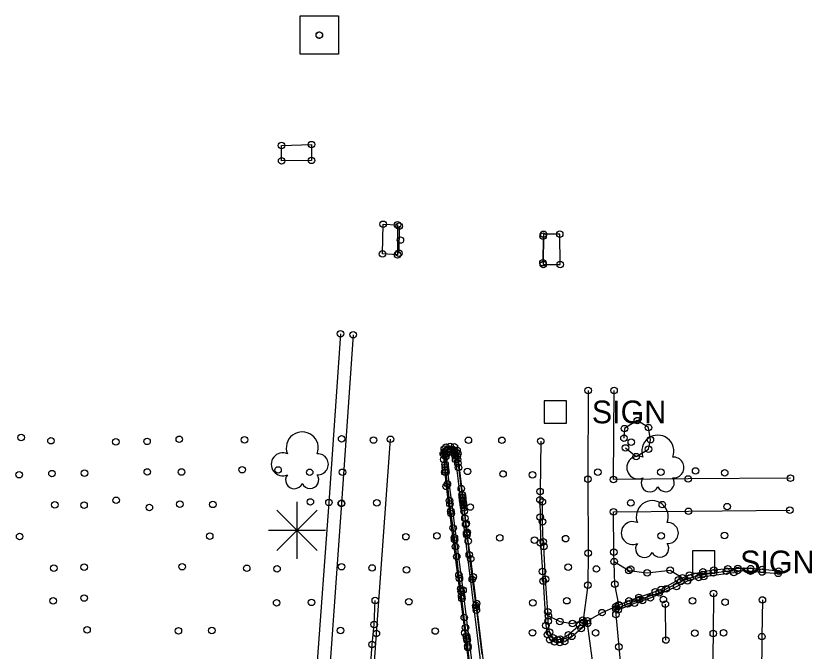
# Model space of a CAD drawing. Extents: x 20503438 to 20508873, y 7964251 to 7984667.
# Drawn here: x 20507965.8 to 20508210.3, y 7970777.7 to 7970972.7 of the extents above; entities that cross this region are included whole.
import ezdxf

# ---------------------------------------------------------------- set-up
doc = ezdxf.new("R2010")
doc.units = 0
for name, color, linetype in [('Default', 7, 'Continuous'), ('SurConcreteSlab', 7, 'Continuous'), ('SurControl', 7, 'Continuous'), ('SurEdgeCurb', 7, 'Continuous'), ('SurEdgeRoadPaved', 7, 'Continuous'), ('SurEdgeSidewalk', 7, 'Continuous'), ('SurMiscStructureLine', 7, 'Continuous'), ('SurNaturalCells', 7, 'Continuous'), ('SurPointsNonDTM', 7, 'Continuous'), ('SurRoadPoints', 7, 'Continuous'), ('SurSurveyPoints', 7, 'Continuous')]:
    doc.layers.add(name, color=color, linetype=linetype)

msp = doc.modelspace()

# ---------------------------------------------------------------- linework, layer by layer
at = {"layer": 'Default'}
msp.add_line((20508058.96, 7970966.8), (20508058.96, 7970966.8), dxfattribs=at)
at = {"layer": 'SurConcreteSlab'}
for points in [[(20508056.53, 7970933.17), (20508056.56, 7970928.33), (20508047.39, 7970928.17), (20508047.33, 7970932.91)], [(20508083.01, 7970899.32), (20508078.36, 7970899.58), (20508078.56, 7970908.71), (20508082.97, 7970908.56)], [(20508127.76, 7970896.34), (20508132.91, 7970896.34), (20508132.8, 7970905.69), (20508127.8, 7970905.63)]]:
    msp.add_lwpolyline(points, close=True, dxfattribs=at)
for points in [[(20508107.6, 7970759.96), (20508103.11, 7970796.34), (20508097.78, 7970837.4), (20508098.06, 7970838.21), (20508098.58, 7970838.71), (20508099.2, 7970838.8), (20508099.97, 7970838.59), (20508100.61, 7970837.86), (20508100.82, 7970836.46), (20508109.87, 7970762.52)], [(20508180.03, 7970795.32), (20508179.96, 7970783.05), (20508179.7, 7970770.56)], [(20508195.04, 7970793.34), (20508194.87, 7970782.09), (20508194.73, 7970769.54), (20508194.52, 7970745.32), (20508194.45, 7970720.76), (20508194.31, 7970696.25), (20508194.23, 7970684.32), (20508194.1, 7970672.27)], [(20508165.42, 7970781.05), (20508165.24, 7970792.03)], [(20508149.99, 7970790.58), (20508150.07, 7970788.88), (20508150.96, 7970778.93), (20508151.97, 7970767.58), (20508152.03, 7970767.48)], [(20508145.82, 7970759.71), (20508145.05, 7970760.17), (20508144.51, 7970760.43), (20508142.73, 7970775.46), (20508141.37, 7970786.17), (20508141.29, 7970786.96)]]:
    msp.add_lwpolyline(points, dxfattribs=at)
at = {"layer": 'SurControl'}
for p, q in [((20508053.08, 7970960.92), (20508053.08, 7970972.68)), ((20508053.08, 7970972.68), (20508064.84, 7970972.68)), ((20508064.84, 7970972.68), (20508064.84, 7970960.92)), ((20508064.84, 7970960.92), (20508053.08, 7970960.92))]:
    msp.add_line(p, q, dxfattribs=at)
at = {"layer": 'SurEdgeCurb'}
for points in [[(20508083.52, 7970908.1), (20508083.37, 7970899.81)], [(20508127.68, 7970905.03), (20508127.64, 7970896.9)], [(20508111.46, 7970757.58), (20508107.28, 7970792.25), (20508106.19, 7970800.48), (20508105.45, 7970805.96), (20508104.72, 7970811.44), (20508104.41, 7970814.12), (20508104.09, 7970816.8), (20508101.55, 7970838.26), (20508101.25, 7970839.35), (20508100.43, 7970840.39), (20508099.17, 7970840.52), (20508097.87, 7970840.26), (20508097.34, 7970839.65), (20508097.04, 7970838.22), (20508097.19, 7970836.5), (20508097.53, 7970832.6), (20508097.91, 7970828.23), (20508103.64, 7970783.23), (20508112.06, 7970713.3)], [(20508105.3, 7970772.87), (20508104.62, 7970778.66), (20508104.56, 7970779.17), (20508104.35, 7970781.01), (20508104.28, 7970781.52), (20508104.19, 7970782.26), (20508103.87, 7970784.83), (20508103.49, 7970787.93), (20508102.76, 7970793.8), (20508102.67, 7970794.53), (20508102.48, 7970795.99), (20508102.38, 7970796.8), (20508101.98, 7970799.94), (20508101.84, 7970801.03), (20508101.15, 7970806.66), (20508100.77, 7970809.73), (20508100.52, 7970811.77), (20508100.44, 7970812.43), (20508100.05, 7970815.43), (20508099.46, 7970819.9), (20508099.36, 7970820.63), (20508099.08, 7970822.82), (20508098.94, 7970823.85), (20508098.29, 7970828.97), (20508097.84, 7970832.56), (20508097.75, 7970833.29), (20508097.64, 7970834.17), (20508097.58, 7970834.97), (20508097.36, 7970837.9), (20508097.55, 7970838.82), (20508098.33, 7970839.5), (20508099.36, 7970839.58), (20508100.31, 7970839.32), (20508100.89, 7970838.7), (20508101.3, 7970837.55), (20508101.41, 7970836.54), (20508101.53, 7970835.38), (20508101.69, 7970833.99), (20508102.56, 7970827.54), (20508102.81, 7970825.63), (20508102.91, 7970824.9), (20508102.94, 7970824.68), (20508103.01, 7970824.09), (20508103.06, 7970823.73), (20508103.12, 7970823.14), (20508103.17, 7970822.77), (20508103.19, 7970822.55), (20508103.3, 7970821.67), (20508103.43, 7970820.57), (20508103.68, 7970818.44), (20508103.9, 7970816.53), (20508104.21, 7970813.88), (20508104.28, 7970813.36), (20508105.02, 7970807.18), (20508105.94, 7970799.68), (20508107.02, 7970791.61), (20508107.09, 7970791.02), (20508107.19, 7970790.21), (20508108.89, 7970776.65)], [(20508138.93, 7970785.58), (20508135.45, 7970782.64), (20508132.99, 7970781.31), (20508132.08, 7970781.12), (20508130.81, 7970781.73), (20508129.68, 7970783.47), (20508129.26, 7970786.83), (20508129.14, 7970789.75), (20508128.46, 7970799.76), (20508127.89, 7970809.74), (20508127.75, 7970811.24), (20508127.5, 7970817.38), (20508127.46, 7970823.44)], [(20508149.99, 7970790.58), (20508153.75, 7970792.12), (20508157.28, 7970793.47), (20508163.38, 7970795.55), (20508165.47, 7970796.77), (20508170.01, 7970799.06), (20508172.82, 7970800.16), (20508176.73, 7970801.21), (20508179.99, 7970801.7), (20508183.98, 7970802.14), (20508187.46, 7970802.38), (20508191.43, 7970802.21), (20508194.93, 7970801.92), (20508199.87, 7970801.51)], [(20508200.05, 7970802.19), (20508194.93, 7970802.74), (20508191.44, 7970802.96), (20508187.48, 7970803.05), (20508184.47, 7970802.89), (20508180.15, 7970802.48), (20508176.8, 7970801.99), (20508172.65, 7970800.98), (20508169.3, 7970799.57), (20508163.96, 7970796.59), (20508162.15, 7970795.85), (20508157.13, 7970794.15), (20508154.07, 7970793.08), (20508151.1, 7970791.7), (20508150.05, 7970791.29)], [(20508074.19, 7970764.53), (20508074.45, 7970769.71), (20508075.14, 7970779.7), (20508075.83, 7970785.82), (20508076.14, 7970793.2)]]:
    msp.add_lwpolyline(points, dxfattribs=at)
at = {"layer": 'SurEdgeRoadPaved'}
for points in [[(20508004.64, 7970575.98), (20508007.59, 7970576.24), (20508010.15, 7970576.78), (20508012.71, 7970577.32), (20508023.73, 7970580.41), (20508026.58, 7970581.33), (20508029.43, 7970582.25), (20508043.66, 7970586.87), (20508052.12, 7970591.56), (20508057.59, 7970595.51), (20508062.67, 7970600.63), (20508065.66, 7970604.97), (20508069.09, 7970611.13), (20508071.43, 7970616.3), (20508072.6, 7970620.21), (20508073.47, 7970624.24), (20508074.25, 7970633.1), (20508074.72, 7970680.34), (20508074.97, 7970737.67), (20508075.09, 7970747.61), (20508075.12, 7970749.94), (20508075.43, 7970766.91), (20508076.47, 7970783.01), (20508080.81, 7970842.69)], [(20508126.95, 7970842.14), (20508126.76, 7970826.65), (20508126.73, 7970824.07), (20508126.8, 7970818.79), (20508126.9, 7970810.87), (20508127.5, 7970802.09), (20508127.7, 7970799.17), (20508128.55, 7970785.48), (20508129.03, 7970782.71), (20508129.77, 7970781.14), (20508131.16, 7970780.45), (20508132.8, 7970780.27), (20508134.32, 7970780.62), (20508136.49, 7970782.18), (20508139.4, 7970784.57), (20508141.37, 7970786.17)], [(20508150.73, 7970790.34), (20508155.76, 7970792.38), (20508158.2, 7970793.19), (20508160.63, 7970793.99), (20508168.7, 7970797.46), (20508172.04, 7970799.24), (20508175.47, 7970800.24), (20508177.05, 7970800.52), (20508186.24, 7970801.76)]]:
    msp.add_lwpolyline(points, dxfattribs=at)
at = {"layer": 'SurEdgeSidewalk'}
for points in [[(20508065.45, 7970875.11), (20508061.91, 7970823.31), (20508058.11, 7970771.65), (20508057.66, 7970725.29), (20508057.57, 7970688.87), (20508054.09, 7970657.04), (20508050.99, 7970628.26), (20508043.75, 7970610.25), (20508036.32, 7970592.17), (20508028.13, 7970591.62), (20508019.27, 7970591.01), (20508019.15, 7970583.11), (20508026.86, 7970581.98)], [(20508069.38, 7970874.8), (20508065.82, 7970823.03), (20508062.04, 7970771.3), (20508061.58, 7970725.29), (20508061.4, 7970688.47), (20508058, 7970656.9), (20508054.87, 7970627.29), (20508047.37, 7970608.68), (20508040.75, 7970592.45), (20508053.1, 7970593.13)], [(20508141.52, 7970857.69), (20508141.46, 7970830.46), (20508141.56, 7970807.74), (20508141.44, 7970797.89), (20508139.87, 7970786.4), (20508141.29, 7970786.96), (20508145.79, 7970789.47), (20508150.05, 7970791.29), (20508150.97, 7970791.83), (20508149.75, 7970798.22), (20508149.41, 7970808.04), (20508149.33, 7970820.39), (20508172.37, 7970820.58), (20508203.46, 7970820.93)], [(20508203.64, 7970830.72), (20508172.24, 7970830.5), (20508149.32, 7970830.31), (20508149.48, 7970857.64)]]:
    msp.add_lwpolyline(points, dxfattribs=at)
at = {"layer": 'SurMiscStructureLine'}
for points in [[(20508153, 7970840.03), (20508156.3, 7970837.36), (20508160.09, 7970839.65), (20508160.65, 7970842.55), (20508160.08, 7970846.27), (20508156.62, 7970848.41), (20508152.7, 7970845.96), (20508152.53, 7970843.04)], [(20508149.53, 7970805.12), (20508154, 7970802.36), (20508159.66, 7970801.67), (20508166.73, 7970802.52), (20508170.52, 7970800.18)], [(20508129.31, 7970788.44), (20508132.82, 7970786.73), (20508136.74, 7970786.14), (20508139.92, 7970787.13)]]:
    msp.add_lwpolyline(points, dxfattribs=at)
at = {"layer": 'SurNaturalCells'}
for p, q in [((20508052.12, 7970806.02), (20508052.12, 7970823.5)), ((20508045.94, 7970808.58), (20508058.3, 7970820.94)), ((20508058.3, 7970808.58), (20508045.94, 7970820.94)), ((20508043.38, 7970814.76), (20508060.86, 7970814.76)), ((20508052.12, 7970814.76), (20508052.12, 7970814.76))]:
    msp.add_line(p, q, dxfattribs=at)
for centre, radius, start, end in [((20508053.72, 7970840.04), 4.92, 338.2051, 201.7949), ((20508162.93, 7970839.04), 4.92, 338.2051, 201.7949), ((20508047.7, 7970835.01), 3.51, 65.4824, 294.5175), ((20508058.52, 7970835.01), 3.21, 265.9982, 94.0018), ((20508156.91, 7970834.01), 3.51, 65.4824, 294.5175), ((20508167.73, 7970834.01), 3.21, 265.9982, 94.0018), ((20508051.29, 7970830.19), 2.68, 142.7501, 335.3223), ((20508056.11, 7970830.27), 2.67, 206.5242, 35.4033), ((20508160.5, 7970829.19), 2.68, 142.7501, 335.3223), ((20508165.32, 7970829.27), 2.67, 206.5242, 35.4033), ((20508161.22, 7970818.92), 4.92, 338.2051, 201.7949), ((20508155.2, 7970813.89), 3.51, 65.4824, 294.5175), ((20508166.02, 7970813.89), 3.21, 265.9982, 94.0018), ((20508158.79, 7970809.07), 2.68, 142.7501, 335.3223), ((20508163.61, 7970809.15), 2.67, 206.5242, 35.4033)]:
    msp.add_arc(centre, radius, start, end, dxfattribs=at)
at = {"layer": 'SurPointsNonDTM'}
for centre in [(20508156.62, 7970848.41), (20508160.08, 7970846.27), (20508152.7, 7970845.96), (20508152.53, 7970843.04), (20508160.65, 7970842.55), (20508153, 7970840.03), (20508160.09, 7970839.65), (20508156.3, 7970837.36), (20508149.53, 7970805.12), (20508154, 7970802.36), (20508166.73, 7970802.52), (20508159.66, 7970801.67), (20508170.52, 7970800.18), (20508129.31, 7970788.44), (20508132.82, 7970786.73), (20508136.74, 7970786.14), (20508139.92, 7970787.13)]:
    msp.add_circle(centre, 1, dxfattribs=at)
at = {"layer": 'SurRoadPoints'}
for points in [[(20508131.45, 7970847.65), (20508131.45, 7970847.65), (20508134.88, 7970847.65), (20508134.88, 7970854.51), (20508128.02, 7970854.51), (20508128.02, 7970847.65), (20508131.45, 7970847.65)], [(20508176.99, 7970801.58), (20508176.99, 7970801.58), (20508180.42, 7970801.58), (20508180.42, 7970808.44), (20508173.56, 7970808.44), (20508173.56, 7970801.58), (20508176.99, 7970801.58)]]:
    msp.add_lwpolyline(points, dxfattribs=at)
at = {"layer": 'SurSurveyPoints'}
for centre in [(20508058.94, 7970966.81), (20508058.96, 7970966.79), (20508058.96, 7970966.79), (20508058.97, 7970966.79), (20508047.33, 7970932.91), (20508056.53, 7970933.17), (20508047.39, 7970928.17), (20508056.56, 7970928.33), (20508078.56, 7970908.71), (20508082.97, 7970908.56), (20508083.52, 7970908.1), (20508127.68, 7970905.03), (20508127.8, 7970905.63), (20508132.8, 7970905.69), (20508083.86, 7970903.86), (20508078.36, 7970899.58), (20508083.01, 7970899.32), (20508083.37, 7970899.81), (20508127.64, 7970896.9), (20508127.76, 7970896.34), (20508132.91, 7970896.34), (20508065.45, 7970875.11), (20508069.38, 7970874.8), (20508141.52, 7970857.69), (20508149.48, 7970857.64), (20507967.39, 7970843.26), (20507976.54, 7970842.24), (20507996.46, 7970841.93), (20508006.04, 7970842.04), (20508015.95, 7970842.68), (20508036, 7970842.49), (20508065.82, 7970842.84), (20508075.62, 7970842.45), (20508080.81, 7970842.69), (20508104.75, 7970842.38), (20508115.05, 7970842.37), (20508126.95, 7970842.14), (20508154.77, 7970841.82), (20508097.34, 7970839.65), (20508097.55, 7970838.82), (20508097.87, 7970840.26), (20508098.33, 7970839.5), (20508099.17, 7970840.52), (20508099.2, 7970838.8), (20508099.36, 7970839.58), (20508100.31, 7970839.32), (20508100.43, 7970840.39), (20508101.25, 7970839.35), (20508097.04, 7970838.22), (20508097.19, 7970836.5), (20508097.36, 7970837.9), (20508097.78, 7970837.4), (20508098.06, 7970838.21), (20508098.58, 7970838.71), (20508099.97, 7970838.59), (20508100.61, 7970837.86), (20508100.82, 7970836.46), (20508100.89, 7970838.7), (20508101.3, 7970837.55), (20508101.41, 7970836.54), (20508101.55, 7970838.26), (20508097.58, 7970834.97), (20508097.64, 7970834.17), (20508101.53, 7970835.38), (20508101.69, 7970833.99), (20507966.77, 7970831.82), (20507976.85, 7970832.15), (20507986.81, 7970832.29), (20508006.13, 7970832.65), (20508016.64, 7970832.64), (20508035.28, 7970833.34), (20508046.29, 7970833.27), (20508056, 7970832.54), (20508066.06, 7970832.56), (20508097.53, 7970832.6), (20508097.75, 7970833.29), (20508097.84, 7970832.56), (20508104.45, 7970832.84), (20508115.39, 7970832.03), (20508124.46, 7970831.78), (20508144.49, 7970832.57), (20508163.85, 7970832.57), (20508174.53, 7970832.95), (20508183.46, 7970832.38), (20508098.29, 7970828.97), (20508141.46, 7970830.46), (20508149.32, 7970830.31), (20508172.24, 7970830.5), (20508203.64, 7970830.72), (20508097.91, 7970828.23), (20508102.56, 7970827.54), (20508126.76, 7970826.65), (20508102.81, 7970825.63), (20508102.91, 7970824.9), (20508102.94, 7970824.68), (20508103.01, 7970824.09), (20507977.7, 7970822.55), (20507986.69, 7970822.45), (20507996.55, 7970823.95), (20508006.75, 7970821.74), (20508016.13, 7970822.76), (20508026.27, 7970822.69), (20508056.2, 7970823.45), (20508061.91, 7970823.31), (20508065.71, 7970822.95), (20508065.82, 7970823.03), (20508076.61, 7970823.2), (20508098.94, 7970823.85), (20508099.08, 7970822.82), (20508103.06, 7970823.73), (20508103.12, 7970823.14), (20508103.17, 7970822.77), (20508103.19, 7970822.55), (20508103.3, 7970821.67), (20508105.34, 7970821.88), (20508126.73, 7970824.07), (20508127.46, 7970823.44), (20508154.66, 7970823.14), (20508164.3, 7970822.62), (20508184.2, 7970822), (20508099.36, 7970820.63), (20508099.46, 7970819.9), (20508103.43, 7970820.57), (20508149.33, 7970820.39), (20508172.37, 7970820.58), (20508203.46, 7970820.93), (20508103.68, 7970818.44), (20508104.09, 7970816.8), (20508126.8, 7970818.79), (20508127.5, 7970817.38), (20508100.05, 7970815.43), (20508103.9, 7970816.53), (20507966.92, 7970812.83), (20508025.29, 7970812.93), (20508085.56, 7970812.78), (20508095.08, 7970813.02), (20508100.44, 7970812.43), (20508104.21, 7970813.88), (20508104.28, 7970813.36), (20508104.41, 7970814.12), (20508114.37, 7970812.44), (20508134.61, 7970812.17), (20508163.95, 7970813.06), (20508183.41, 7970813.13), (20508100.52, 7970811.77), (20508100.77, 7970809.73), (20508104.72, 7970811.44), (20508125.04, 7970811.7), (20508126.9, 7970810.87), (20508127.75, 7970811.24), (20508127.89, 7970809.74), (20508105.02, 7970807.18), (20508141.56, 7970807.74), (20508149.41, 7970808.04), (20508101.15, 7970806.66), (20508105.45, 7970805.96), (20507977.42, 7970803.13), (20507986.71, 7970803.4), (20508016.81, 7970803.56), (20508036.66, 7970803.08), (20508045.96, 7970802.9), (20508065.76, 7970803.56), (20508075.16, 7970803.18), (20508085.73, 7970802.59), (20508127.5, 7970802.09), (20508135.38, 7970803.4), (20508144.05, 7970802.86), (20508154.59, 7970802.8), (20508180.15, 7970802.48), (20508183.98, 7970802.14), (20508184.47, 7970802.89), (20508187.46, 7970802.38), (20508187.48, 7970803.05), (20508191.43, 7970802.21), (20508191.44, 7970802.96), (20508194.93, 7970802.74), (20508200.05, 7970802.19), (20508101.84, 7970801.03), (20508101.98, 7970799.94), (20508105.94, 7970799.68), (20508106.19, 7970800.48), (20508128.46, 7970799.76), (20508172.65, 7970800.98), (20508172.82, 7970800.16), (20508175.47, 7970800.24), (20508176.73, 7970801.21), (20508176.8, 7970801.99), (20508177.05, 7970800.52), (20508179.99, 7970801.7), (20508186.24, 7970801.76), (20508194.93, 7970801.92), (20508199.87, 7970801.51), (20508127.7, 7970799.17), (20508141.44, 7970797.89), (20508149.75, 7970798.22), (20508168.7, 7970797.46), (20508169.3, 7970799.57), (20508170.01, 7970799.06), (20508172.04, 7970799.24), (20508102.38, 7970796.8), (20508102.48, 7970795.99), (20508103.11, 7970796.34), (20508162.15, 7970795.85), (20508163.38, 7970795.55), (20508163.96, 7970796.59), (20508165.47, 7970796.77), (20508180.03, 7970795.32), (20507977.23, 7970793.06), (20507986.72, 7970793.95), (20508045.85, 7970792.45), (20508056.56, 7970792.62), (20508076.14, 7970793.2), (20508086.47, 7970792.82), (20508102.67, 7970794.53), (20508102.76, 7970793.8), (20508124.56, 7970792.45), (20508135, 7970793.11), (20508154.07, 7970793.08), (20508155.76, 7970792.38), (20508157.13, 7970794.15), (20508157.28, 7970793.47), (20508158.2, 7970793.19), (20508160.63, 7970793.99), (20508164.63, 7970793.48), (20508173.56, 7970793.06), (20508183.58, 7970792.67), (20508195.04, 7970793.34), (20508107.02, 7970791.61), (20508107.09, 7970791.02), (20508107.19, 7970790.21), (20508107.28, 7970792.25), (20508149.99, 7970790.58), (20508150.05, 7970791.29), (20508150.73, 7970790.34), (20508150.97, 7970791.83), (20508151.1, 7970791.7), (20508153.75, 7970792.12), (20508165.24, 7970792.03), (20508103.49, 7970787.93), (20508129.14, 7970789.75), (20508145.79, 7970789.47), (20508150.07, 7970788.88), (20508075.83, 7970785.82), (20508128.55, 7970785.48), (20508129.26, 7970786.83), (20508138.93, 7970785.58), (20508139.87, 7970786.4), (20508141.29, 7970786.96), (20508141.29, 7970786.96), (20508141.37, 7970786.17), (20507987.62, 7970784.2), (20508015.67, 7970783.86), (20508025.92, 7970783.97), (20508065.44, 7970783.95), (20508076.47, 7970783.01), (20508094.58, 7970783.81), (20508103.64, 7970783.23), (20508103.87, 7970784.83), (20508124.41, 7970783.29), (20508129.03, 7970782.71), (20508129.68, 7970783.47), (20508135.45, 7970782.64), (20508139.4, 7970784.57), (20508143.83, 7970783.25), (20508174.29, 7970783.14), (20508179.96, 7970783.05), (20508183.14, 7970783.28), (20508104.19, 7970782.26), (20508104.28, 7970781.52), (20508104.35, 7970781.01), (20508129.77, 7970781.14), (20508130.81, 7970781.73), (20508131.16, 7970780.45), (20508132.08, 7970781.12), (20508132.8, 7970780.27), (20508132.99, 7970781.31), (20508134.32, 7970780.62), (20508136.49, 7970782.18), (20508165.42, 7970781.05), (20508194.87, 7970782.09), (20508075.14, 7970779.7), (20508104.56, 7970779.17), (20508104.62, 7970778.66), (20508150.96, 7970778.93)]:
    msp.add_circle(centre, 1, dxfattribs=at)

# ---------------------------------------------------------------- texts
at = {"layer": 'SurRoadPoints'}
for p in [(20508142.66, 7970847.58), (20508188.2, 7970801.51)]:
    msp.add_text('SIGN', height=6.995, rotation=360, dxfattribs=at).set_placement(p)

doc.saveas('drawing.dxf')
